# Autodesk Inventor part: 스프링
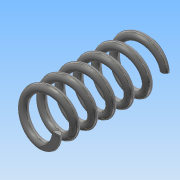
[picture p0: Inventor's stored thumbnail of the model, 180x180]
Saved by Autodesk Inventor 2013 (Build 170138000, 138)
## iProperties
Created: 2015-12
Part Number: 스프링
Material: 강철, 탄소
Document SubType Name: Modeling
Designer: Administrator
Density: 7.87 g/cm^3
Mass: 16.5231 g
Surface Area: 28.4697 cm^2
Volume: 2.0995 cm^3
Author: Administrator
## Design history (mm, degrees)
sketch "스케치1"
  geometry: L1 (0, 0)-(0, 42); L2 (0, 42)-(8, 42); L3 (0, 0)-(8, 0); C1 r 1.5 at (8, 0)
  constraints: 6 end point, 1 centre point, 1 coincident, 1 parallel, 1 perpendicular, 1 vertical
  dimensions: "d0" = 42 distance of L1.start L1.end (derived); "d1" = 8 distance of L1.end L2.end; "d2" = 8 distance of L1.start L3.end; "d3" = 3 diameter of C1
feature "코일1" sketch "스케치1" pitch "d4" = 10; turns "d6" = 6; dims "d5" = 42 (= d0), "d7" = 0, angle "d8" = 90 deg, angle "d9" = 90 deg, "d10" = 0, "d11" = 0
sketch "스케치2"
  geometry: L1 (0, 12.5)-(42, 12.5); L2 (42, 12.5)-(42, -12.5); L3 (42, -12.5)-(0, -12.5); L4 (0, -12.5)-(0, 12.5); 2 further points
  constraints: 8 end point, 2 parallel, 1 coincident, 1 horizontal, 1 midpoint, 1 perpendicular
  dimensions: "d12" = 42 distance of L1.start L1.end (derived); "d14" = 25 distance of L1.end L2.end
extrude "돌출1" sketch "스케치2" stored distance "d15" = 10; taper "d16" = 0 deg
node "솔리드1"
